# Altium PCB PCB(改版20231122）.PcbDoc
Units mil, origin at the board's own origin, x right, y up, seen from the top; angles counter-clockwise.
Board outline 3903.82 x 2740.03 mil, 2 copper layers (Top Layer, Bottom Layer); 31 components, 55 nets, 141 pads, 3 vias.
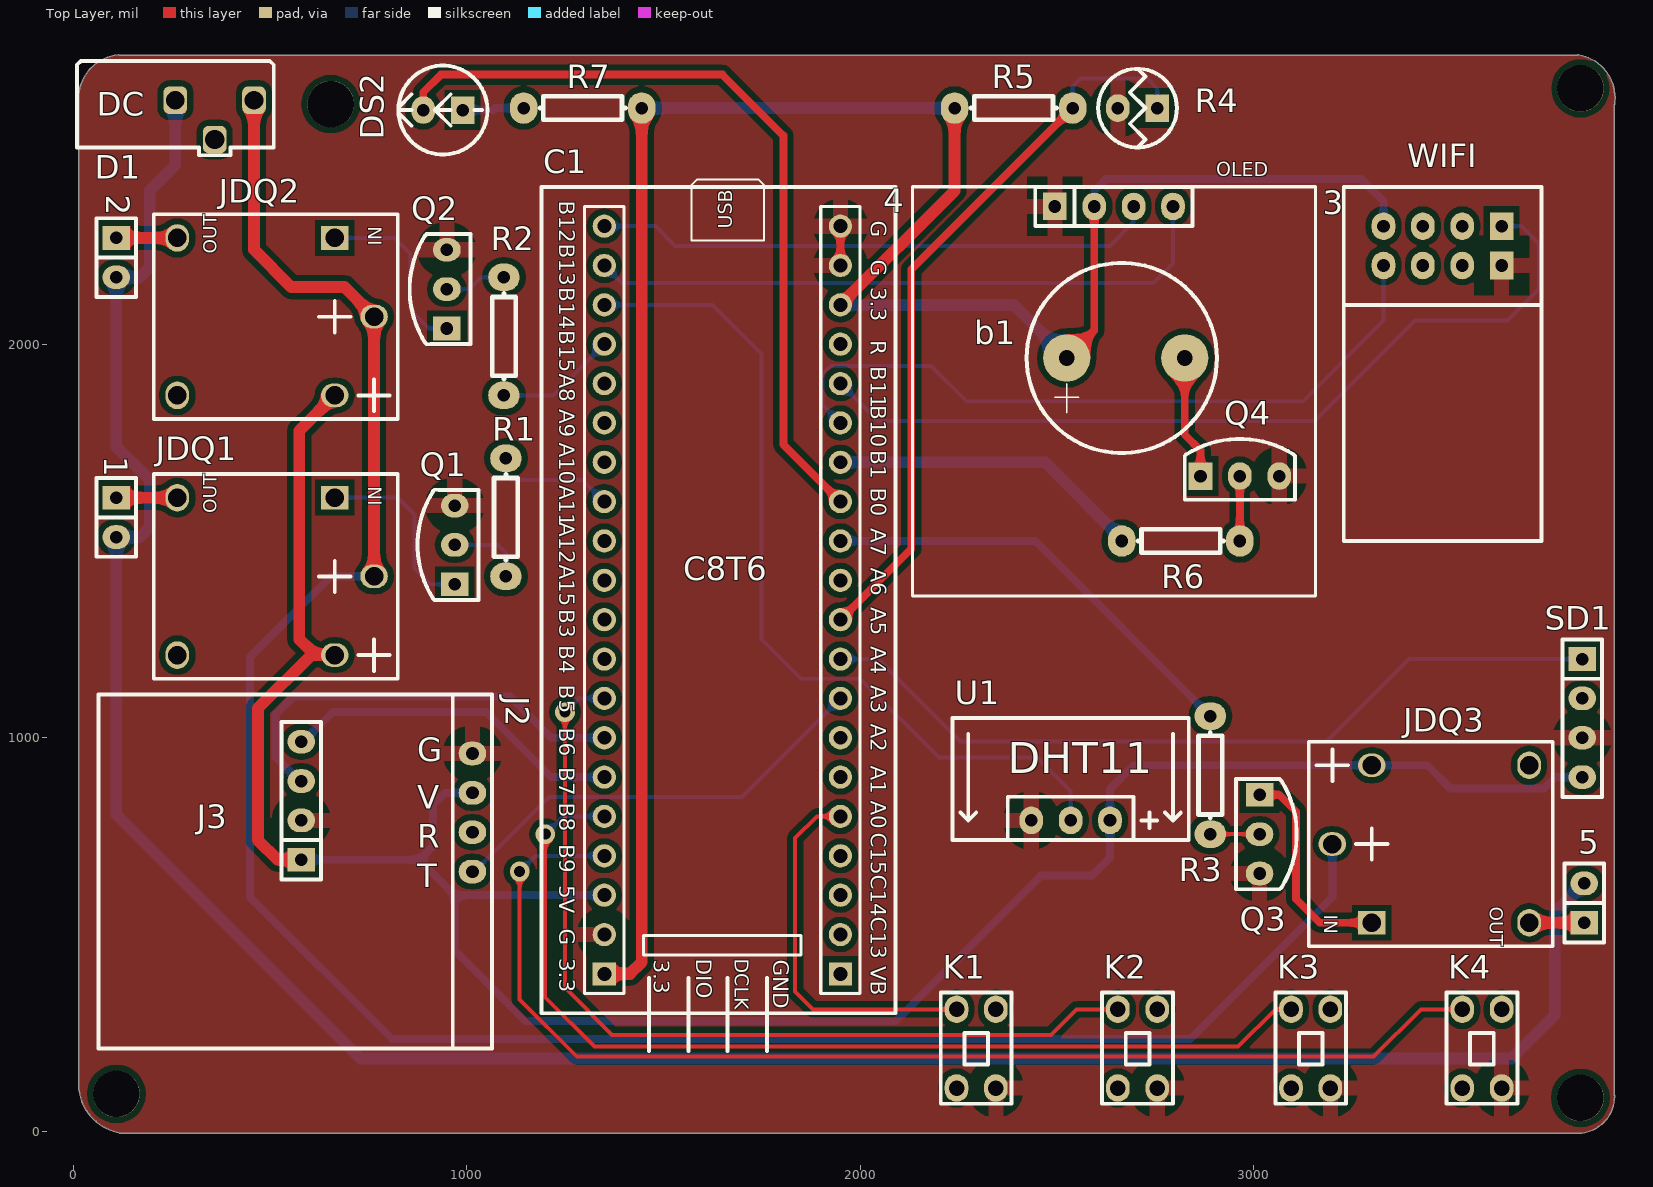
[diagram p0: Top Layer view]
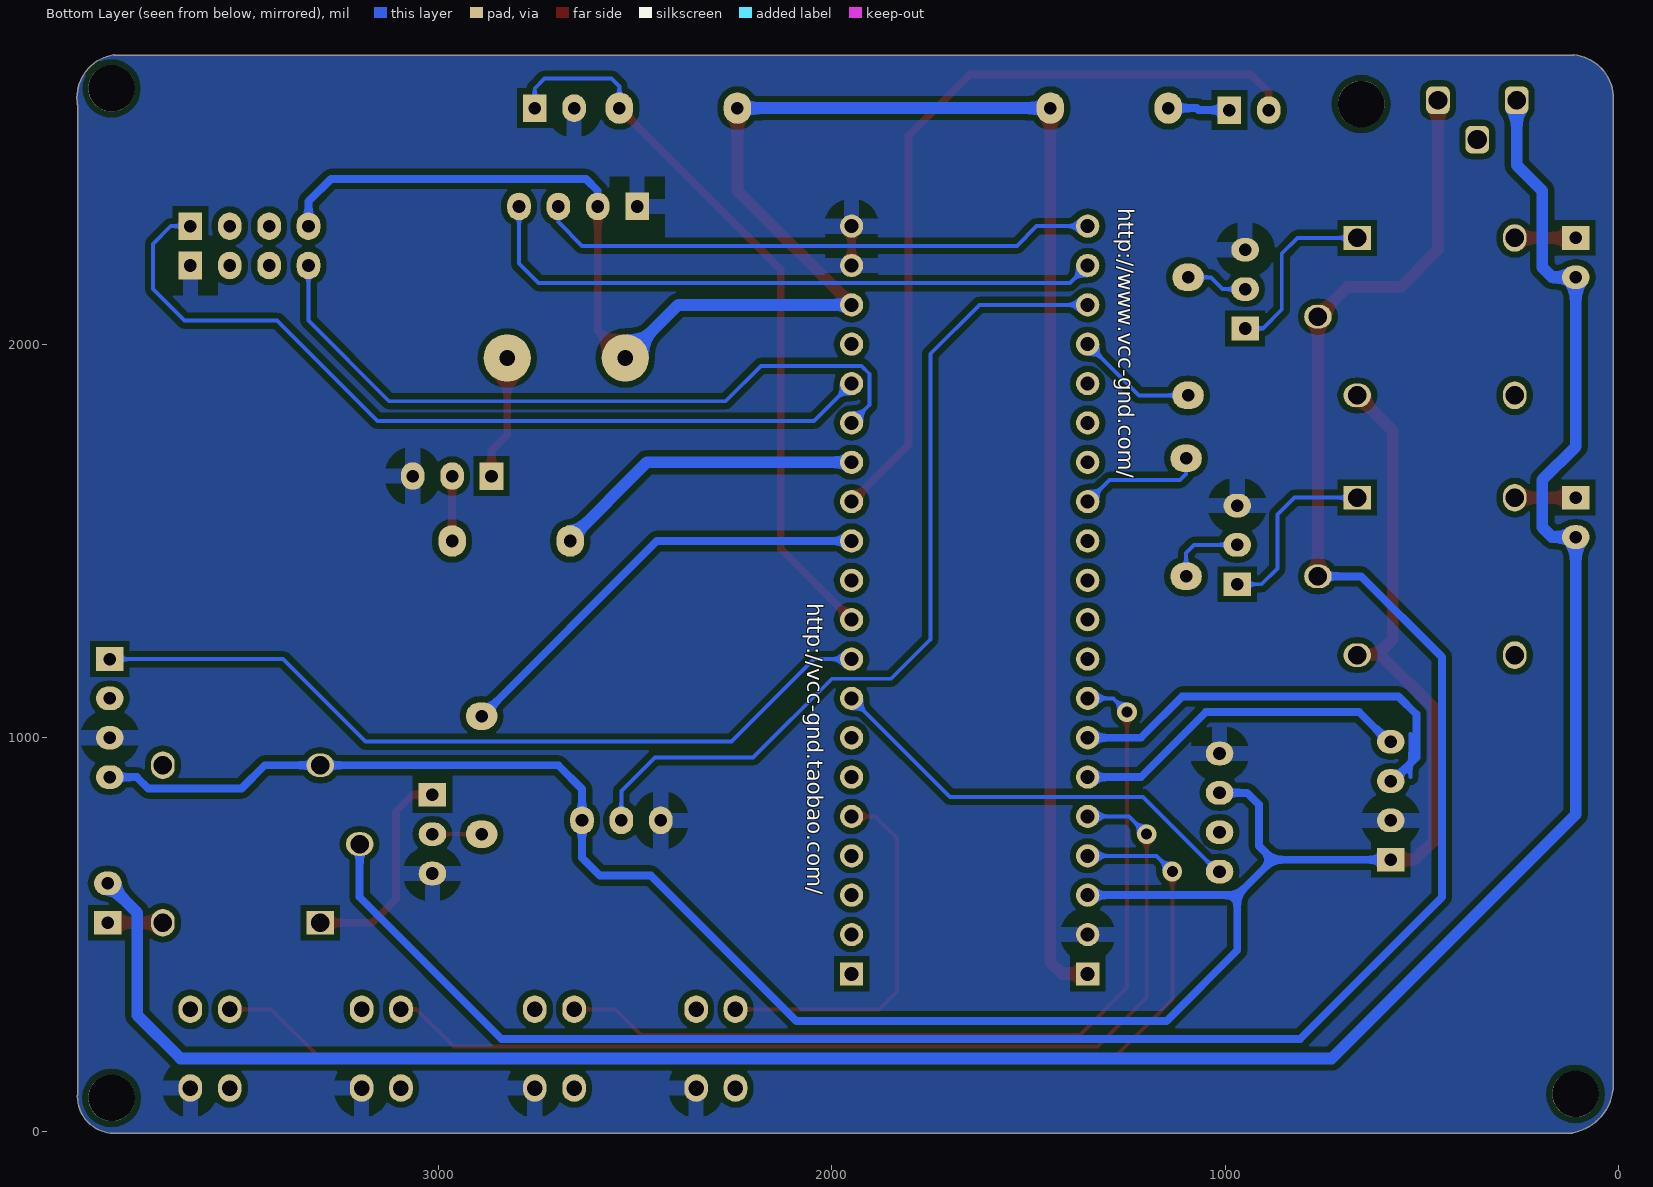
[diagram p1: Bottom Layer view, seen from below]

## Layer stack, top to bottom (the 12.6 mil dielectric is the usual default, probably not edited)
Top Solder: solder mask 0.4, Solder Resist, Dk 3.5
Top Layer: signal copper 1.4
Dielectric 1: dielectric 12.6, FR-4, Dk 4.8
Bottom Layer: signal copper 1.4
Bottom Solder: solder mask 0.4, Solder Resist, Dk 3.5

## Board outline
116.43,-3.26 cw(c139.27,119.27) 15,128.92 cw(c20,128.53) 15.16,129.85 15.16,2613.68 cw(c20,2615) 15.01,2614.52 cw(c125,2625) 114.52,2734.99 cw(c115,2730) 116.32,2734.84 3823.68,2734.84 cw(c3825,2730) 3825.79,2734.95 cw(c3808.5,2626.5) 3918.33,2626.5 cw(c3808.5,2626.5) 3916.96,2609.21 cw(c3912.01,2610) 3916.85,2608.68 3916.85,91.32 cw(c3912.01,90) 3917.02,90.08 cw(c3823.5,88.5) 3917.04,88.5 cw(c3823.5,88.5) 3825.08,-5.01 cw(c3825,0) 3823.68,-4.84 131.32,-4.84 cw(c130,0) 129.61,-5 cw(c139.27,119.27) 127.71,-4.84 120,-4.84 cw(c120,0)

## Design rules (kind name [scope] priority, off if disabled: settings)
Clearance [All] p1: gap=15 ignorepadtopadclearanceinfootprint=FALSE
DiffPairsRouting [All] p1: maxlimit=10 minlimit=10 mostfreqgap=10 toplayer_minwidth=15 toplayer_maxwidth=100 toplayer_prefwidth=15 bottomlayer_minwidth=15 bottomlayer_maxwidth=100 bottomlayer_prefwidth=15 maxuncoupledlength=500
PolygonConnect [All] p1: connectstyle=Relief reliefconductorwidth=40 reliefentries=4 polygonreliefangle="90 Angle" airgapwidth=40
RoutingVias [All] p1: holewidth=28 width=50 viastyle="Through Hole" minholewidth=28 minwidth=50 maxholewidth=28 maxwidth=50
SolderMaskExpansion [All] p1: expansion=4
Width Width_3 [InNet('VCC3.3')] p1: maxlimit=100 minlimit=20 preferedwidth=20
Width Width_2 [InNet('VCC')] p2: maxlimit=100 minlimit=20 preferedwidth=20
Width Width_1 [InNet('GND')] p3: maxlimit=100 minlimit=20 preferedwidth=20
Width [All] p4: maxlimit=100 minlimit=10 preferedwidth=20
29 further rules are at their usual default settings.

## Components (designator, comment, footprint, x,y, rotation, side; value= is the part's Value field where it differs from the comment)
1 "排扇" SIP2 110,1560 r270 top
2 "水泵" SIP2 110,2220 r270 top
3 "CK" ESP-01S 3630,2300 r180 top
4 "OLED屏幕" OLED 2645,2350 r0 top
5 "水泵" SIP2 3840,580 r90 top
b1 "BELL" bell 2665,1965 r180 top
C1 "核心板" C8T6核心板 1190,300 r0 top
D1 "DC" DC3.5-1.3 0,2460 r0 top
DS2 "照明灯" "LED - duplicate1" 1060,2715 r180 top
J2 "CON4" JW01 1015,1100 r0 top locked
J3 "CON4" SIP4 580,840 r90 top
JDQ1 "继电器" 5继电器 665,1210 r90 top
JDQ2 "继电器" 5继电器 665,1870 r90 top
JDQ3 "继电器" 5继电器 3300,930 r270 top
K1 "KEY" KeyA 2205,350 r0 top
K2 "KEY" KeyA 2615,350 r0 top
K3 "KEY" KeyA 3055,350 r0 top
K4 "KEY" KeyA 3490,350 r0 top
Q1 "NPN" S9013 970,1390 r90 top
Q2 "NPN" S9013 950,2040 r90 top
Q3 "NPN" S9013 3015,855 r270 top
Q4 "NPN" S9013 2865,1665 r0 top
R1 "330R" AXIAL0.3 1100,1560 r270 top
R2 "330R" AXIAL0.3 1095,2020 r90 top
R3 "330R" AXIAL0.3 2890,905 r270 top
R4 "光敏电阻" GM_R 2825,2660 r180 top
R5 "10K" AXIAL0.3 2390,2600 r180 top
R6 "330R" AXIAL0.3 2815,1500 r0 top
R7 "330欧" AXIAL0.3 1295,2600 r180 top
SD1 "SD" SIP4 3835,1050 r270 top
U1 "DHT11" DHT11 2175,730 r0 top

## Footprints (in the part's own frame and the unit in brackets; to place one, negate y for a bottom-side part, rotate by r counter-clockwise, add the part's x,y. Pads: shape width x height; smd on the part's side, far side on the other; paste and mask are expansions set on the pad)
5继电器 [mil]
  rect 60x70 hole 47: 1(400,0)
  oval 60x70 hole 47: 2(200,-100) 3(0,0)
  oval 70x60 hole 47: 4(400,400) 5(0,400)
  silkscreen extent -60,-160 460,460
AXIAL0.3 [mil]
  oval 70x80 hole 32: 1(-150,0) 2(150,0)
  silkscreen extent -109,-30 109,30
bell [mil]
  round 120 hole 40: 1(-160,0) 2(140,0)
  silkscreen extent -242,-242 242,242
C8T6核心板 [mm]
  round 1.5 hole 0.9: 1(4.064,50.8) 2(4.064,48.26) 3(4.064,45.72) 4(4.064,43.18) 5(4.064,40.64) 6(4.064,38.1) 7(4.064,35.56) 8(4.064,33.02) 9(4.064,30.48) 10(4.064,27.94) 11(4.064,25.4) 12(4.064,22.86) 13(4.064,20.32) 14(4.064,17.78) 15(4.064,15.24) 16(4.064,12.7) 17(4.064,10.16) 18(4.064,7.62) 19(4.064,5.08) 22(19.304,5.08) 23(19.304,7.62) 24(19.304,10.16) 25(19.304,12.7) 26(19.304,15.24) 27(19.304,17.78) 28(19.304,20.32) 29(19.304,22.86) 30(19.304,25.4) 31(19.304,27.94) 32(19.304,30.48) 33(19.304,33.02) 34(19.304,35.56) 35(19.304,38.1) 36(19.304,40.64) 37(19.304,43.18) 38(19.304,45.72) 39(19.304,48.26) 40(19.304,50.8)
  rect 1.5x1.5 hole 0.9: 20(4.064,2.54) 21(19.304,2.54)
  silkscreen extent 0,0 22.86,53.34
DC3.5-1.3 [mil]
  rrect50% 60x70 hole 47.24: 1(460,160) 3(260,160)
  rrect50% 60x70 hole 49.21: 2(360,60)
  silkscreen extent 10,20 510,260
DHT11 [mil]
  oval 60x70 hole 32: 1(460,60) 2(360,60) 3(260,60)
  silkscreen extent 60,10 660,320
ESP-01S [mil]
  oval 60x70 hole 32: 1(300,100) 4(300,0) ""(100,100) ""(100,0) ""(200,0) ""(200,100)
  rect 60x70 hole 32: 2(0,0) 3(0,100)
  silkscreen extent -101,-100 401,800
GM_R [mil]
  rect 60x70 hole 32: 1(70,60)
  oval 60x70 hole 32: 2(170,60)
  silkscreen extent 20,-40 220,160
JW01 [mil]
  oval 70x60 hole 32: 1(0,-440) 2(0,-340) 3(0,-240) 4(0,-140)
  silkscreen extent -950,-890 50,10
KeyA [mil]
  oval 60x70 hole 39.37: 1(40,-40) 2(40,-240) 3(140,-240) 4(140,-40)
  silkscreen extent 0,-280 180,3
"LED - duplicate1" [mil]
  rect 60x70 hole 32: 1(70,120)
  oval 60x70 hole 32: 2(170,120)
  silkscreen extent 7,7 233,233
OLED [mil]
  rect 60x70 hole 32: 1(-150,0)
  oval 60x70 hole 32: 2(-50,0) 3(50,0) 4(150,0)
  silkscreen extent -512,-990 512,50
S9013 [mil]
  oval 60x70 hole 32: B(100,0) E(200,0)
  rect 60x70 hole 32: C(0,0)
  silkscreen extent -40,-60 240,94
SIP2 [mil]
  rect 60x70 hole 32: 1(-50,0)
  oval 60x70 hole 32: 2(50,0)
  silkscreen extent -100,-50 100,50
SIP4 [mil]
  rect 60x70 hole 32: 1(-150,0)
  oval 60x70 hole 32: 2(-50,0) 3(50,0) 4(150,0)
  silkscreen extent -200,-50 200,50

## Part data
2 3 5: library part 排扇
4: library part OLED_4
C1: library part C, "电容"
D1: library part DC3.5-1.3
DS2: library part LED, "Typical RED, GREEN, YELLOW, AMBER GaAs LED"
J2: library part "Header 4", "Header, 4-Pin"
JDQ1 JDQ2 JDQ3: library part 4脚继电器
K1 K2 K3 K4: library part key_4pin
R1: library part 光敏电阻
R2 R3 R4 R5 R6 R7: library part RES0603, "电阻"
SD1: library part 土壤湿度传感器

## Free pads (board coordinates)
  round 118.11 hole 118.11 unplated: 0(110,95) 0(655,2610) 0(3830,85) 0(3830,2650)

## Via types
v1: diameter 50, hole 28, Top Layer to Bottom Layer, 3 vias

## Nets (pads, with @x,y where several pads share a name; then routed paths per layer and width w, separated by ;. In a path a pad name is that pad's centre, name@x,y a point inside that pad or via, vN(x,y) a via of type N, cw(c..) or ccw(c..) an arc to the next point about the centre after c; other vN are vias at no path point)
GND: 3.3 4.1 C1.19 C1.39 C1.40 J2.4 J3.2 K1.3 K2.3 K3.3 K4.3 Q1.E Q2.E Q3.E Q4.E R4.2 SD1.3 U1.3 | length 103.1
  Top Layer w20: C1.39 1949.93,2200.07 1949.93,2299.93 C1.40 ; R4.2@2655,2597 R4.2
GND1: 1.2 2.2 5.2 D1.3 | length 6341.3
  Bottom Layer w30: D1.3 260,2455 195,2390 195,2195 170,2170 2.2 110,1740 195,1655 195,1535 170,1510 1.2 110,805 730,185 3655,185 3765,295 3765,555 5.2
Net1_1: 1.1 JDQ1.4 | length 155
  Top Layer w30: 1.1 JDQ1.4
Net2_1: 2.1 JDQ2.4 | length 155
  Top Layer w30: 2.1 JDQ2.4
Net5_1: 5.1 JDQ3.4 | length 140
  Top Layer w30: JDQ3.4 5.1
Netb1_1: b1.1 Q4.C | length 316.6
  Top Layer w20: b1.1 2825,1770 2865,1730 Q4.C
NetBT1_1: C1.21
NetDJ1_1: 
NetDJ1_2: 
NetDJ1_3: 
NetDJ1_4: 
NetDS2_1: DS2.1 R7.2 | length 157.1
  Bottom Layer w20: DS2.1 1068,2595 1073,2600 R7.2
NetJDQ1_1: JDQ1.1 Q1.C | length 476.4
  Bottom Layer w10: JDQ1.1 825,1610 868,1567 868,1430 908,1390 Q1.C
NetJDQ2_1: JDQ2.1 Q2.C | length 463.5
  Bottom Layer w10: JDQ2.1 817,2270 857,2230 857,2088 905,2040 Q2.C
NetJDQ3_1: JDQ3.1 Q3.C | length 549.7
  Top Layer w20: Q3.C 3065,855 3108,812 3108,590 3168,530 JDQ3.1
NetQ1_B: Q1.B R1.2 | length 198.3
  Bottom Layer w10: Q1.B 1080,1490 1100,1470 R1.2
NetQ2_B: Q2.B R2.2 | length 157.4
  Bottom Layer w10: Q2.B 1007,2140 1037,2170 R2.2
NetQ3_B: Q3.B R3.2 | length 125
  Top Layer w10: R3.2 Q3.B
NetQ4_B: Q4.B R6.2 | length 165
  Top Layer w20: R6.2 Q4.B
PA0: C1.25 K1.1 | length 956.4
  Top Layer w10: C1.25 1890,800 1835,745 1835,355 1880,310 K1.1
PA1: C1.26
PA2: C1.27 | length 10
  Top Layer w10: C1.27 C1.27@1960,1000
PA3: C1.28 J2.1 | length 1117.3
  Bottom Layer w10: J2.1 1020,660 1210,850 1700,850 C1.28
PA4: C1.29 SD1.1 | length 2059
  Bottom Layer w10: C1.29 2045,1200 2255,990 3185,990 3395,1200 SD1.1
PA5: C1.30 R4.1 R5.1 | length 1883
  Top Layer w20: C1.30 2130,1480 2130,2190 R5.1
  Bottom Layer w10: R5.1 2540,2655 2560,2675 2730,2675 2755,2650 R4.1
PA6: C1.31
PA7: C1.32 R3.1 | length 1124.3
  Bottom Layer w20: C1.32 2445,1500 R3.1
PA8: C1.5
PA9: C1.6
PA10: C1.7
PA11: C1.8 R1.1 | length 319
  Bottom Layer w10: R1.1 1100,1670 1115,1655 1295,1655 C1.8
PA12: C1.9
PA15: C1.10
PB0: C1.33 DS2.2 | length 2032.9
  Top Layer w20: DS2.2 890,2640 935,2685 1650,2685 1805,2530 1805,1745 C1.33
PB1: C1.34 R6.1 | length 800.8
  Bottom Layer w30: C1.34 2470,1700 2665,1505 R6.1
PB2: C1.37
PB3: C1.11
PB4: C1.12
PB5: C1.13 K2.1 | length 2296.1
  Top Layer w10: v1(1250,1065) 1250,365 1370,245 2485,245 2550,310 K2.1
  Bottom Layer w10: v1(1250,1065) 1285,1100 C1.13
PB6: C1.14 J3.3 | length 1207
  Top Layer w20: J3.3@575,890 J3.3
  Bottom Layer w10: 530,900 530,935 530,1010
  Bottom Layer w20: J3.3@575,890 530,935 515,950 515,1060 560,1105 1110,1105 1215,1000 C1.14
PB7: C1.15 J3.4 | length 869.4
  Top Layer w20: J3.4 J3.4@585,990
  Bottom Layer w20: J3.4@585,990 660,1065 1050,1065 1215,900 C1.15
PB8: C1.16 K3.1 | length 2576.8
  Top Layer w10: v1(1200,755) 1200,340 1325,215 2960,215 3055,310 K3.1 ; C1.16@1345,795 C1.16
  Bottom Layer w10: v1(1200,755) 1245,800 C1.16
PB9: C1.17 K4.1 | length 3061.3
  Top Layer w10: v1(1135,660) 1135,335 1280,190 3305,190 3425,310 K4.1
  Bottom Layer w10: v1(1135,660) 1175,700 C1.17
PB10: 3.1 C1.35 | length 1839.1
  Bottom Layer w10: C1.35 1905,1845 1905,1925 1925,1945 2180,1945 2270,1855 3125,1855 3330,2060 3.1
PB11: 3.2 C1.36 | length 2181.8
  Bottom Layer w10: C1.36 2045,1805 3155,1805 3410,2060 3645,2060 3725,2140 3725,2255 3680,2300 3.2
PB12: 4.3 C1.1 | length 1430.6
  Bottom Layer w10: C1.1 1480,2300 1530,2250 2635,2250 2695,2310 4.3
PB13: 4.4 C1.2 | length 1629.4
  Bottom Layer w10: C1.2 1395,2155 2745,2155 2795,2205 4.4
PB14: C1.3 U1.2 | length 2196.2
  Bottom Layer w10: C1.3 1625,2100 1750,1975 1750,1250 1850,1150 2000,1150 2200,950 2450,950 2535,865 U1.2
PB15: C1.4 R2.1 | length 308.8
  Bottom Layer w10: R2.1 1220,1870 C1.4
PC13: C1.22
PC14: C1.23
PC15: C1.24
VCC: C1.18 J2.3 J3.1 JDQ1.3 JDQ2.3 JDQ3.3 SD1.4 U1.1 | length 5992.4
  Top Layer w30: J3.1 520,690 470,740 470,1075 605,1210 615,1210 ; JDQ1.3 615,1210 ; JDQ2.3 575,1780 575,1250 615,1210
  Bottom Layer w20: J3.1 880,690 ; J2.3 945,860 915,830 915,725 880,690 ; C1.18 970,600 ; SD1.4 3766,900 3737,871 3500,871 3441,930 JDQ3.3 2695,930 2635,870 U1.1 2635,695 2590,650 2460,650 2090,280 1150,280 970,460 970,600 ; 880,690 970,600
VCC1: D1.1 JDQ1.2 JDQ2.2 JDQ3.2 | length 5613.6
  Top Layer w30: D1.1 460,2240 555,2145 690,2145 JDQ2.2 JDQ1.2
  Bottom Layer w20: JDQ1.2@770,1410 JDQ1.2 655,1410 450,1205 450,595 810,235 2840,235 3200,595 JDQ3.2
VCC3.3: 3.4 4.2 b1.2 C1.20 C1.38 R5.2 R7.1 | length 5611.5
  Top Layer w20: b1.2 2595,2035 4.2
  Top Layer w30: C1.20 1415,400 1445,430 1445,2595 R7.1 ; C1.38 2240,2390 R5.2
  Bottom Layer w20: 4.2 2595,2390 2625,2420 3273,2420 3330,2363 3.4
  Bottom Layer w30: R7.1 R5.2 ; C1.38 2390,2100 b1.2
pads on no net: 3. D1.2 J2.2 JDQ1.5 JDQ2.5 JDQ3.5 K1.2 K1.4 K2.2 K2.4 K3.2 K3.4 K4.2 K4.4 SD1.2

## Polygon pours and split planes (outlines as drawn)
GND on Bottom Layer "GND_L02_P006" (solid, remove dead copper, pour order 6): 116.43,-3.26 cw(c139.27,119.27) 15,128.92 cw(c20,128.53) 15.16,129.85 15.16,2613.68 cw(c20,2615) 15.01,2614.52 cw(c125,2625) 114.52,2734.99 cw(c115,2730) 116.32,2734.84 3823.68,2734.84 cw(c3825,2730) 3825.79,2734.95 cw(c3808.5,2626.5) 3918.33,2626.5 cw(c3808.5,2626.5) 3916.96,2609.21 cw(c3912.01,2610) 3916.85,2608.68 3916.85,91.32 cw(c3912.01,90) 3917.02,90.08 cw(c3823.5,88.5) 3917.04,88.5 cw(c3823.5,88.5) 3825.08,-5.01 cw(c3825,0) 3823.68,-4.84 131.32,-4.84 cw(c130,0) 129.61,-5 cw(c139.27,119.27) 127.71,-4.84 120,-4.84 cw(c120,0)
GND on Top Layer "GND_L01_P007" (solid, remove dead copper, pour order 7): 116.43,-3.26 cw(c139.27,119.27) 15,128.92 cw(c20,128.53) 15.16,129.85 15.16,2613.68 cw(c20,2615) 15.01,2614.52 cw(c125,2625) 114.52,2734.99 cw(c115,2730) 116.32,2734.84 3823.68,2734.84 cw(c3825,2730) 3825.79,2734.95 cw(c3808.5,2626.5) 3918.33,2626.5 cw(c3808.5,2626.5) 3916.96,2609.21 cw(c3912.01,2610) 3916.85,2608.68 3916.85,91.32 cw(c3912.01,90) 3917.02,90.08 cw(c3823.5,88.5) 3917.04,88.5 cw(c3823.5,88.5) 3825.08,-5.01 cw(c3825,0) 3823.68,-4.84 131.32,-4.84 cw(c130,0) 129.61,-5 cw(c139.27,119.27) 127.71,-4.84 120,-4.84 cw(c120,0)

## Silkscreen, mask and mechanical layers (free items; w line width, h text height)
Top Overlay:
  lines w5: 1571.38,2263.66 1571.38,2403.66 1586.38,2418.66 1741.38,2418.66 1756.38,2403.66 1756.38,2263.66 1751.38,2263.66 1571.38,2263.66
  lines w10: 1463.82,204.17 1463.82,389.17 ; 1563.53,204.17 1563.53,389.17 ; 1663.24,204.17 1663.24,389.17 ; 1762.95,204.17 1762.95,389.17
  text "USB" at 1686.38,2293.66 h60 r90
Mechanical 1:
  lines w9.65: 20,128.53 20,2615 ; 115,2730 260,2730 3825,2730 ; 120,0 3825,0 ; 3912.01,90 3912.01,2610
  lines w10: 20,128.53 ccw(c139.27,119.27) 130,0 ; 20,2615 cw(c125,2625) 115,2730 ; 3825,0 ccw(c3823.5,88.5) 3912.01,90 ; 3825,2730 cw(c3808.5,2626.5) 3912.01,2610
